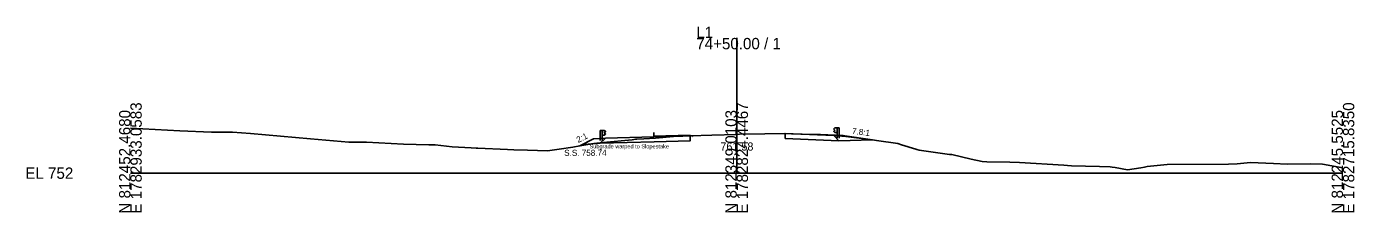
# Model space of a CAD drawing. Extents: x 5574 to 10203, y -10 to 9546.
# Drawn here: x 8574.3 to 8902.8, y 2490.3 to 2536.2 of the extents above; entities that cross this region are included whole.
import ezdxf

# ---------------------------------------------------------------- set-up
doc = ezdxf.new("R2010")
doc.units = 0
for name, color, linetype in [('Exist Cross Section Cell', 7, 'Continuous'), ('Exist XS Center Line Elevation Label', 7, 'Continuous'), ('Exist XS Ground Line', 7, 'Continuous'), ('Prop XS Ditch Slope Text', 7, 'Continuous'), ('Prop XS Dump Level', 7, 'Continuous'), ('Prop XS Earthwork Shape', 7, 'Continuous'), ('Prop XS EOT Tick Mark', 7, 'Continuous'), ('Prop XS Finish Grade', 7, 'Continuous'), ('Prop XS Finish Grade Earthwork', 7, 'Continuous'), ('Prop XS Finish Grade Paved Shoulder', 7, 'Continuous'), ('Prop XS Finish Grade Pavement', 7, 'Continuous'), ('Prop XS Guardrail', 7, 'Continuous'), ('Prop XS Hydro Fill Slope Data', 7, 'Continuous'), ('Prop XS Pvmt Edge Slope', 7, 'Continuous'), ('Prop XS Side Slope Text', 7, 'Continuous'), ('Prop XS SS Elevation Text', 7, 'Continuous'), ('Prop XS Subgrade Earthwork', 7, 'Continuous'), ('Scratch_Level_3', 7, 'Continuous'), ('Scratch_Level_6', 7, 'Continuous')]:
    doc.layers.add(name, color=color, linetype=linetype)

msp = doc.modelspace()

# ---------------------------------------------------------------- linework, layer by layer
at = {"layer": 'Exist Cross Section Cell'}
for p, q in [((8750, 2500), (8750, 2533.4)), ((8600, 2500), (8750, 2500)), ((8750, 2500), (8900, 2500))]:
    msp.add_line(p, q, dxfattribs=at)
at = {"layer": 'Exist XS Ground Line'}
for p, q in [((8600, 2511.13), (8612.22, 2510.42)), ((8612.22, 2510.42), (8620.06, 2510.14)), ((8620.06, 2510.14), (8620.69, 2510.15)), ((8620.69, 2510.15), (8625.27, 2510.16)), ((8625.27, 2510.16), (8629.7, 2509.77)), ((8629.7, 2509.77), (8644.53, 2508.44)), ((8644.53, 2508.44), (8654.06, 2507.68)), ((8654.06, 2507.68), (8658.4, 2507.69)), ((8658.4, 2507.69), (8667.6, 2507.2)), ((8667.6, 2507.2), (8673.83, 2506.99)), ((8673.83, 2506.99), (8675.39, 2507.01)), ((8675.39, 2507.01), (8679.58, 2506.51)), ((8709.48, 2506.41), (8711.21, 2506.76)), ((8711.21, 2506.76), (8713.16, 2507.04)), ((8713.16, 2507.04), (8714.67, 2507.33)), ((8714.67, 2507.33), (8716.99, 2507.6)), ((8716.99, 2507.6), (8724.14, 2508.27)), ((8724.14, 2508.27), (8724.95, 2508.36)), ((8724.95, 2508.36), (8725.27, 2508.38)), ((8725.27, 2508.38), (8727.04, 2508.48)), ((8727.04, 2508.48), (8729.94, 2508.66)), ((8729.94, 2508.66), (8734.37, 2509.05)), ((8734.37, 2509.05), (8736.68, 2509.17)), ((8736.68, 2509.17), (8738.52, 2509.26)), ((8738.52, 2509.26), (8743.82, 2509.41)), ((8743.82, 2509.41), (8750, 2509.58)), ((8750, 2509.58), (8750.69, 2509.6)), ((8750.69, 2509.6), (8757, 2509.71)), ((8757, 2509.71), (8761.74, 2509.8)), ((8761.74, 2509.8), (8763.59, 2509.72)), ((8763.59, 2509.72), (8765.85, 2509.63)), ((8765.85, 2509.63), (8770.77, 2509.56)), ((8770.77, 2509.56), (8772.57, 2509.48)), ((8772.57, 2509.48), (8776.37, 2509.3)), ((8776.37, 2509.3), (8776.78, 2509.23)), ((8776.78, 2509.23), (8783.62, 2508.22)), ((8783.62, 2508.22), (8784.63, 2508.08)), ((8784.63, 2508.08), (8789.83, 2507.29)), ((8789.83, 2507.29), (8790.76, 2507.02)), ((8790.76, 2507.02), (8794.3, 2505.92)), ((8679.58, 2506.51), (8684.3, 2506.27)), ((8684.3, 2506.27), (8685.53, 2506.17)), ((8685.53, 2506.17), (8685.95, 2506.14)), ((8685.95, 2506.14), (8693.32, 2505.84)), ((8693.32, 2505.84), (8694.89, 2505.8)), ((8694.89, 2505.8), (8698.23, 2505.64)), ((8698.23, 2505.64), (8703.19, 2505.5)), ((8703.19, 2505.5), (8706.06, 2505.95)), ((8706.06, 2505.95), (8709.48, 2506.41)), ((8794.3, 2505.92), (8794.61, 2505.83)), ((8794.61, 2505.83), (8795.15, 2505.67)), ((8795.15, 2505.67), (8802.67, 2504.62)), ((8802.67, 2504.62), (8803.25, 2504.65)), ((8803.25, 2504.65), (8808.04, 2503.47)), ((8808.04, 2503.47), (8810.73, 2502.84)), ((8810.73, 2502.84), (8811.88, 2502.82)), ((8811.88, 2502.82), (8817.54, 2502.69)), ((8817.54, 2502.69), (8819.94, 2502.63)), ((8819.94, 2502.63), (8830.92, 2501.98)), ((8830.92, 2501.98), (8831.84, 2501.88)), ((8831.84, 2501.88), (8832.84, 2501.84)), ((8832.84, 2501.84), (8839.78, 2501.62)), ((8839.78, 2501.62), (8842.44, 2501.54)), ((8842.44, 2501.54), (8842.87, 2501.52)), ((8842.87, 2501.52), (8843.68, 2501.38)), ((8843.68, 2501.38), (8846.7, 2500.86)), ((8846.7, 2500.86), (8849.97, 2501.32)), ((8849.97, 2501.32), (8850.89, 2501.45)), ((8850.89, 2501.45), (8851.55, 2501.61)), ((8851.55, 2501.61), (8856.54, 2502.12)), ((8856.54, 2502.12), (8871.67, 2502.24)), ((8871.67, 2502.24), (8873.79, 2502.32)), ((8873.79, 2502.32), (8877.12, 2502.61)), ((8877.12, 2502.61), (8882.78, 2502.35)), ((8882.78, 2502.35), (8886.16, 2502.23)), ((8886.16, 2502.23), (8891.96, 2502.29)), ((8891.96, 2502.29), (8894.93, 2502.24)), ((8894.93, 2502.24), (8900, 2501.35))]:
    msp.add_line(p, q, dxfattribs=at)
at = {"layer": 'Prop XS Dump Level'}
msp.add_line((8738.52, 2509.35), (8729.54, 2509.17), dxfattribs=at)
at = {"layer": 'Prop XS Earthwork Shape'}
for points in [[(8711.16, 2506.74), (8711.21, 2506.76), (8713.16, 2507.04), (8714.05, 2507.21), (8711.72, 2507.03)], [(8714.05, 2507.21), (8714.67, 2507.33), (8716.99, 2507.6), (8724.14, 2508.27), (8724.95, 2508.36), (8725.27, 2508.38), (8727.04, 2508.48), (8729.94, 2508.66), (8734.37, 2509.05), (8736.68, 2509.17), (8738.53, 2509.26), (8738.53, 2508.01), (8729.57, 2507.76), (8716.25, 2507.39)], [(8762, 2508.54), (8775.3, 2508.01), (8783.62, 2508.22), (8776.78, 2509.23), (8776.37, 2509.3), (8772.57, 2509.48), (8770.77, 2509.56), (8765.85, 2509.63), (8763.59, 2509.72), (8762, 2509.79)]]:
    msp.add_lwpolyline(points, close=True, dxfattribs=at)
at = {"layer": 'Prop XS EOT Tick Mark'}
msp.add_line((8729.54, 2509.01), (8729.54, 2510.01), dxfattribs=at)
at = {"layer": 'Prop XS Finish Grade'}
for p, q in [((8714.54, 2508.44), (8711.72, 2507.03)), ((8717.54, 2508.68), (8714.54, 2508.44)), ((8774, 2509.31), (8777, 2509.07)), ((8777, 2509.07), (8783.62, 2508.22))]:
    msp.add_line(p, q, dxfattribs=at)
at = {"layer": 'Prop XS Finish Grade Earthwork'}
msp.add_line((8711.72, 2507.03), (8711.16, 2506.74), dxfattribs=at)
at = {"layer": 'Prop XS Finish Grade Paved Shoulder'}
msp.add_line((8729.54, 2509.01), (8717.54, 2508.68), dxfattribs=at)
at = {"layer": 'Prop XS Finish Grade Pavement'}
for p, q in [((8738.53, 2509.26), (8729.54, 2509.01)), ((8762, 2509.79), (8774, 2509.31))]:
    msp.add_line(p, q, dxfattribs=at)
at = {"layer": 'Prop XS Guardrail'}
for p, q in [((8716.22, 2510.55), (8716.72, 2510.55)), ((8716.22, 2508.05), (8716.22, 2510.55)), ((8716.72, 2510.55), (8717.22, 2510.55)), ((8716.72, 2510.55), (8716.72, 2508.05)), ((8717.22, 2510.55), (8717.51, 2510.35)), ((8717.51, 2510.23), (8717.22, 2510.03)), ((8717.22, 2510.03), (8717.22, 2509.94)), ((8717.51, 2510.35), (8717.54, 2510.29)), ((8717.54, 2510.29), (8717.51, 2510.23)), ((8774.03, 2510.98), (8774, 2510.92)), ((8774, 2510.92), (8774.03, 2510.86)), ((8774.03, 2510.37), (8774, 2510.31)), ((8774, 2510.31), (8774.03, 2510.25)), ((8774.32, 2511.18), (8774.03, 2510.98)), ((8774.03, 2510.86), (8774.32, 2510.66)), ((8774.32, 2510.57), (8774.03, 2510.37)), ((8774.03, 2510.25), (8774.32, 2510.05)), ((8774.82, 2511.18), (8774.32, 2511.18)), ((8774.32, 2510.66), (8774.32, 2510.57)), ((8774.32, 2510.05), (8774.82, 2510.05)), ((8775.32, 2511.18), (8774.82, 2511.18)), ((8774.82, 2511.18), (8774.82, 2508.68)), ((8775.32, 2508.68), (8775.32, 2511.18)), ((8717.22, 2509.42), (8716.72, 2509.42)), ((8717.22, 2509.94), (8717.51, 2509.74)), ((8717.51, 2509.62), (8717.22, 2509.42)), ((8717.51, 2509.74), (8717.54, 2509.68)), ((8717.54, 2509.68), (8717.51, 2509.62))]:
    msp.add_line(p, q, dxfattribs=at)
at = {"layer": 'Prop XS Hydro Fill Slope Data'}
msp.add_line((8714.54, 2508.44), (8711.16, 2506.74), dxfattribs=at)
at = {"layer": 'Prop XS Pvmt Edge Slope'}
for p, q in [((8717.54, 2508.68), (8716.25, 2507.39)), ((8774, 2509.31), (8775.3, 2508.01))]:
    msp.add_line(p, q, dxfattribs=at)
at = {"layer": 'Prop XS Subgrade Earthwork'}
for p, q in [((8716.25, 2507.39), (8711.72, 2507.03)), ((8729.57, 2507.76), (8716.25, 2507.39)), ((8738.53, 2508.01), (8729.57, 2507.76)), ((8738.53, 2508.01), (8738.53, 2509.26)), ((8762, 2508.54), (8762, 2509.79)), ((8762, 2508.54), (8775.3, 2508.01)), ((8775.3, 2508.01), (8783.62, 2508.22))]:
    msp.add_line(p, q, dxfattribs=at)
at = {"layer": 'Scratch_Level_3'}
for p, q in [((8714.54, 2508.44), (8711.72, 2507.03)), ((8711.72, 2507.03), (8716.25, 2507.39)), ((8717.54, 2508.68), (8714.54, 2508.44)), ((8716.25, 2507.39), (8717.54, 2508.68)), ((8777, 2509.07), (8774, 2509.31)), ((8774, 2509.31), (8775.3, 2508.01)), ((8775.3, 2508.01), (8783.62, 2508.22)), ((8783.62, 2508.22), (8777, 2509.07))]:
    msp.add_line(p, q, dxfattribs=at)
at = {"layer": 'Scratch_Level_6'}
for points in [[(8734.37, 2509.05), (8736.68, 2509.17), (8738.53, 2509.26), (8738.53, 2508.01), (8729.57, 2507.76), (8716.25, 2507.39), (8714.05, 2507.21), (8714.67, 2507.33), (8716.99, 2507.6), (8724.14, 2508.27), (8724.95, 2508.36), (8725.27, 2508.38), (8727.04, 2508.48), (8729.94, 2508.66)], [(8762, 2508.54), (8762, 2509.79), (8763.59, 2509.72), (8765.85, 2509.63), (8766.2, 2509.62), (8774, 2509.31), (8777, 2509.07), (8783.62, 2508.22), (8775.3, 2508.01)]]:
    msp.add_lwpolyline(points, close=True, dxfattribs=at)

# ---------------------------------------------------------------- texts
at = {"layer": 'Exist Cross Section Cell'}
for s, p in [('74+50.00 / 1', (8740, 2530.6)), ('L1', (8740, 2533.4)), ('EL 752', (8574, 2498.6))]:
    msp.add_text(s, height=2.8, dxfattribs=at).set_placement(p)
for s, p in [('E 1782933.0583', (8602.8, 2490)), ('E 1782824.4467', (8752.8, 2490)), ('E 1782715.8350', (8902.8, 2490)), ('N 812452.4680', (8600, 2490)), ('N 812349.0103', (8750, 2490)), ('N 812245.5525', (8900, 2490))]:
    msp.add_text(s, height=2.8, rotation=90, dxfattribs=at).set_placement(p)
at = {"layer": 'Exist XS Center Line Elevation Label'}
msp.add_text('761.58', height=2, dxfattribs=at).set_placement((8745.96, 2505.58))
at = {"layer": 'Prop XS Ditch Slope Text'}
msp.add_text('7.8:1', height=1.5, rotation=352.6992, dxfattribs=at).set_placement((8778.46, 2509.72))
at = {"layer": 'Prop XS Dump Level'}
for s, height, p in [('Subgrade warped to Slopestake', 1, (8713.59, 2506.13)), ('Case4', 0.04, (8717.54, 2508.22)), ('Eop', 0.3, (8738.53, 2508.96))]:
    msp.add_text(s, height=height, dxfattribs=at).set_placement(p)
at = {"layer": 'Prop XS Side Slope Text'}
msp.add_text('2:1', height=1.5, rotation=26.5651, dxfattribs=at).set_placement((8710.8, 2507.45))
at = {"layer": 'Prop XS SS Elevation Text'}
msp.add_text('S.S. 758.74', height=1.5, dxfattribs=at).set_placement((8707.32, 2504.28))

doc.saveas('drawing.dxf')
